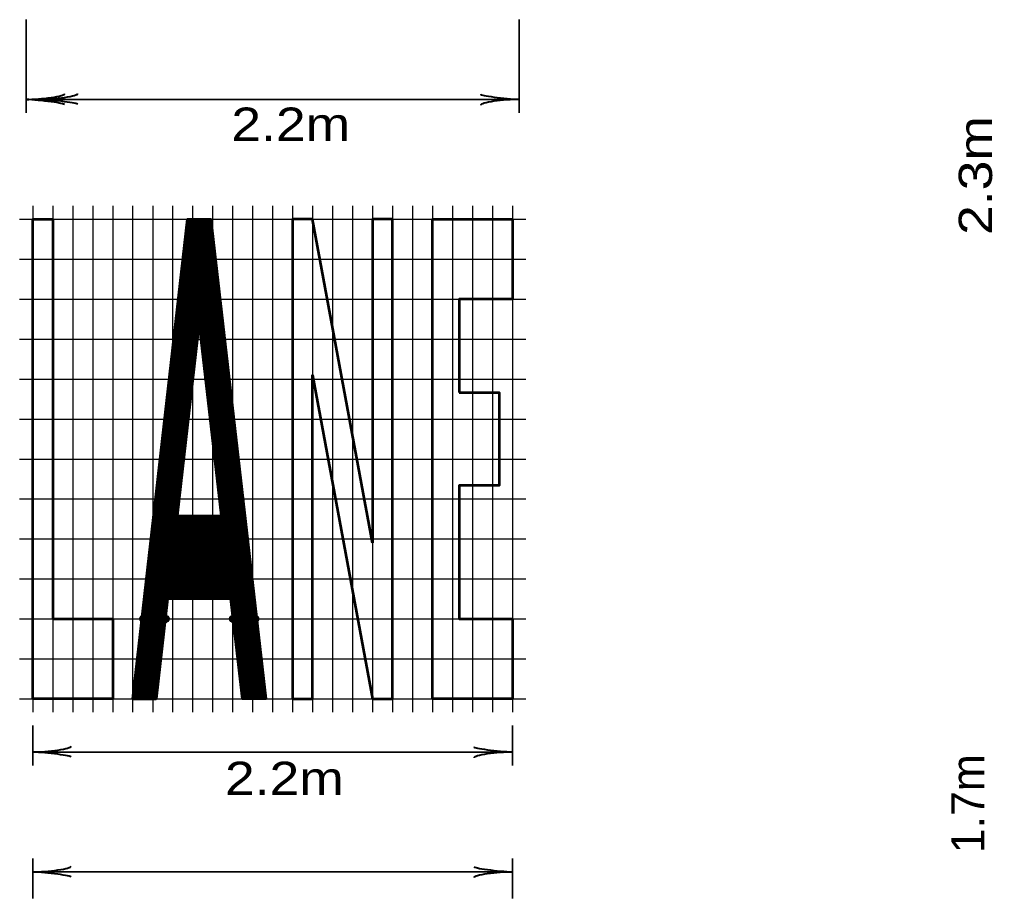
# Model space of a CAD drawing. Extents: x -96 to 617, y -65 to 388.
# Drawn here: x 37.8 to 110.8, y 261.3 to 327.3 of the extents above; entities that cross this region are included whole.
import ezdxf
from ezdxf.enums import TextEntityAlignment as Align

# ---------------------------------------------------------------- set-up
doc = ezdxf.new("R2010")
doc.units = 0
doc.header["$PDMODE"] = 32
doc.header["$PDSIZE"] = 0.5
doc.layers.add('1', color=7, linetype='Continuous', lineweight=53)

msp = doc.modelspace()

# ---------------------------------------------------------------- linework, layer by layer
at = {"layer": '1', "lineweight": 35}
for p, q in [((38.29, 327.267), (38.29, 320.267)), ((75.29, 327.267), (75.29, 320.267)), ((38.29, 321.267), (75.29, 321.267)), ((38.79, 274.267), (38.79, 271.267)), ((74.79, 274.267), (74.79, 271.267)), ((38.79, 272.267), (74.79, 272.267)), ((38.79, 264.267), (38.79, 261.267)), ((74.79, 264.267), (74.79, 261.267)), ((74.79, 263.267), (38.79, 263.267))]:
    msp.add_line(p, q, dxfattribs=at)
at = {"layer": '1', "lineweight": 25}
for p, q in [((38.79, 313.267), (38.79, 275.267)), ((40.29, 313.267), (40.29, 275.267)), ((41.79, 313.267), (41.79, 275.267)), ((43.29, 313.267), (43.29, 275.267)), ((44.79, 313.267), (44.79, 275.267)), ((46.29, 275.267), (46.29, 313.267)), ((47.79, 313.267), (47.79, 275.267)), ((49.29, 313.267), (49.29, 275.267)), ((50.79, 313.267), (50.79, 275.267)), ((52.29, 313.267), (52.29, 275.267)), ((53.79, 313.267), (53.79, 275.267)), ((55.29, 313.267), (55.29, 275.267)), ((56.79, 313.267), (56.79, 275.267)), ((58.29, 313.267), (58.29, 275.267)), ((59.79, 313.267), (59.79, 275.267)), ((61.29, 313.267), (61.29, 275.267)), ((62.79, 313.267), (62.79, 275.267)), ((64.29, 313.267), (64.29, 275.267)), ((65.79, 313.267), (65.79, 275.267)), ((67.29, 313.267), (67.29, 275.267)), ((68.79, 313.267), (68.79, 275.267)), ((70.29, 313.267), (70.29, 275.267)), ((71.79, 313.267), (71.79, 275.267)), ((73.29, 313.267), (73.29, 275.267)), ((74.79, 313.267), (74.79, 275.267)), ((37.79, 312.267), (75.79, 312.267)), ((37.79, 309.267), (75.79, 309.267)), ((37.79, 306.267), (75.79, 306.267)), ((37.79, 303.267), (75.79, 303.267)), ((37.79, 300.267), (75.79, 300.267)), ((37.79, 297.267), (75.79, 297.267)), ((37.79, 294.267), (75.79, 294.267)), ((37.79, 291.267), (75.79, 291.267)), ((37.79, 288.267), (75.79, 288.267)), ((37.79, 285.267), (75.79, 285.267)), ((37.79, 282.267), (75.79, 282.267)), ((37.79, 279.267), (75.79, 279.267)), ((37.79, 276.267), (75.79, 276.267))]:
    msp.add_line(p, q, dxfattribs=at)
at = {"layer": '1'}
for p, q in [((50.137, 309.84), (52.206, 311.91)), ((50.16, 310.04), (52.188, 312.068)), ((50.183, 310.24), (52.17, 312.227)), ((50.206, 310.44), (52.034, 312.267)), ((50.229, 310.639), (51.857, 312.267)), ((50.252, 310.839), (51.68, 312.267)), ((50.275, 311.038), (51.503, 312.267)), ((50.297, 311.238), (51.327, 312.267)), ((50.32, 311.438), (51.15, 312.267)), ((50.343, 311.637), (50.973, 312.267)), ((50.366, 311.837), (50.796, 312.267)), ((50.389, 312.037), (50.619, 312.267)), ((50.412, 312.236), (50.443, 312.267)), ((50.046, 309.042), (52.279, 311.275)), ((50.069, 309.242), (52.261, 311.434)), ((50.092, 309.441), (52.243, 311.592)), ((50.114, 309.641), (52.225, 311.751)), ((49.931, 308.044), (52.37, 310.482)), ((49.954, 308.243), (52.352, 310.641)), ((49.977, 308.443), (52.334, 310.799)), ((50, 308.643), (52.315, 310.958)), ((50.023, 308.842), (52.297, 311.116)), ((49.84, 307.245), (52.443, 309.848)), ((49.863, 307.445), (52.424, 310.006)), ((49.886, 307.644), (52.406, 310.165)), ((49.909, 307.844), (52.388, 310.323)), ((49.726, 306.247), (52.533, 309.055)), ((49.748, 306.446), (52.515, 309.213)), ((49.771, 306.646), (52.497, 309.372)), ((49.794, 306.846), (52.479, 309.531)), ((49.817, 307.045), (52.461, 309.689)), ((49.611, 305.248), (52.624, 308.262)), ((49.634, 305.448), (52.606, 308.42)), ((49.657, 305.648), (52.588, 308.579)), ((49.68, 305.847), (52.57, 308.738)), ((49.703, 306.047), (52.552, 308.896)), ((49.52, 304.45), (52.697, 307.627)), ((49.543, 304.649), (52.679, 307.786)), ((49.565, 304.849), (52.661, 307.945)), ((49.588, 305.049), (52.643, 308.103)), ((49.405, 303.452), (52.788, 306.834)), ((49.428, 303.651), (52.77, 306.993)), ((49.451, 303.851), (52.752, 307.151)), ((49.474, 304.051), (52.733, 307.31)), ((49.497, 304.25), (52.715, 307.469)), ((49.314, 302.653), (52.861, 306.2)), ((49.337, 302.853), (52.843, 306.358)), ((49.36, 303.052), (52.824, 306.517)), ((49.382, 303.252), (52.806, 306.676)), ((51.298, 304.461), (52.879, 306.041)), ((51.317, 304.302), (52.897, 305.883)), ((51.335, 304.144), (52.915, 305.724)), ((51.353, 303.985), (52.933, 305.565)), ((51.371, 303.826), (52.951, 305.407)), ((51.389, 303.668), (52.97, 305.248)), ((51.407, 303.509), (52.988, 305.09)), ((51.426, 303.351), (53.006, 304.931)), ((51.444, 303.192), (53.024, 304.772)), ((51.462, 303.033), (53.042, 304.614)), ((49.245, 302.054), (51.235, 304.043)), ((49.268, 302.254), (51.257, 304.243)), ((49.291, 302.453), (51.28, 304.443)), ((51.48, 302.875), (53.06, 304.455)), ((51.498, 302.716), (53.079, 304.297)), ((51.517, 302.558), (53.097, 304.138)), ((51.535, 302.399), (53.115, 303.979)), ((49.154, 301.255), (51.143, 303.245)), ((49.176, 301.455), (51.166, 303.445)), ((49.199, 301.655), (51.189, 303.644)), ((49.222, 301.854), (51.212, 303.844)), ((51.553, 302.24), (53.133, 303.821)), ((51.571, 302.082), (53.151, 303.662)), ((51.589, 301.923), (53.17, 303.504)), ((51.607, 301.765), (53.188, 303.345)), ((51.626, 301.606), (53.206, 303.186)), ((49.062, 300.457), (51.051, 302.446)), ((49.085, 300.656), (51.074, 302.646)), ((49.108, 300.856), (51.097, 302.846)), ((49.131, 301.056), (51.12, 303.045)), ((51.644, 301.447), (53.224, 303.028)), ((51.662, 301.289), (53.242, 302.869)), ((51.68, 301.13), (53.26, 302.711)), ((51.698, 300.972), (53.279, 302.552)), ((48.993, 299.858), (50.983, 301.847)), ((49.016, 300.058), (51.006, 302.047)), ((49.039, 300.257), (51.029, 302.246)), ((51.716, 300.813), (53.297, 302.393)), ((51.735, 300.654), (53.315, 302.235)), ((51.753, 300.496), (53.333, 302.076)), ((51.771, 300.337), (53.351, 301.918)), ((51.789, 300.179), (53.369, 301.759)), ((48.902, 299.059), (50.891, 301.049)), ((48.925, 299.259), (50.914, 301.248)), ((48.948, 299.459), (50.937, 301.448)), ((48.971, 299.658), (50.96, 301.648)), ((51.807, 300.02), (53.388, 301.6)), ((51.825, 299.861), (53.406, 301.442)), ((51.844, 299.703), (53.424, 301.283)), ((51.862, 299.544), (53.442, 301.125)), ((51.88, 299.385), (53.46, 300.966)), ((48.81, 298.261), (50.8, 300.25)), ((48.833, 298.46), (50.823, 300.45)), ((48.856, 298.66), (50.846, 300.649)), ((48.879, 298.86), (50.868, 300.849)), ((51.898, 299.227), (53.478, 300.807)), ((51.916, 299.068), (53.497, 300.649)), ((51.934, 298.91), (53.515, 300.49)), ((51.953, 298.751), (53.533, 300.332)), ((48.742, 297.662), (50.731, 299.651)), ((48.765, 297.861), (50.754, 299.851)), ((48.788, 298.061), (50.777, 300.05)), ((51.971, 298.592), (53.551, 300.173)), ((51.989, 298.434), (53.569, 300.014)), ((52.007, 298.275), (53.588, 299.856)), ((52.025, 298.117), (53.606, 299.697)), ((52.044, 297.958), (53.624, 299.538)), ((48.65, 296.863), (50.64, 298.852)), ((48.673, 297.063), (50.663, 299.052)), ((48.696, 297.262), (50.685, 299.252)), ((48.719, 297.462), (50.708, 299.451)), ((52.062, 297.799), (53.642, 299.38)), ((52.08, 297.641), (53.66, 299.221)), ((52.098, 297.482), (53.678, 299.063)), ((52.116, 297.324), (53.697, 298.904)), ((48.559, 296.064), (50.548, 298.054)), ((48.582, 296.264), (50.571, 298.253)), ((48.605, 296.464), (50.594, 298.453)), ((48.627, 296.663), (50.617, 298.653)), ((52.134, 297.165), (53.715, 298.745)), ((52.153, 297.007), (53.733, 298.587)), ((52.171, 296.848), (53.751, 298.428)), ((52.189, 296.689), (53.769, 298.27)), ((52.207, 296.531), (53.788, 298.111)), ((48.49, 295.465), (50.48, 297.455)), ((48.513, 295.665), (50.502, 297.654)), ((48.536, 295.865), (50.525, 297.854)), ((52.225, 296.372), (53.806, 297.952)), ((52.243, 296.214), (53.824, 297.794)), ((52.262, 296.055), (53.842, 297.635)), ((52.28, 295.896), (53.86, 297.477)), ((52.298, 295.738), (53.878, 297.318)), ((48.399, 294.667), (50.388, 296.656)), ((48.422, 294.866), (50.411, 296.856)), ((48.444, 295.066), (50.434, 297.055)), ((48.467, 295.266), (50.457, 297.255)), ((52.316, 295.579), (53.896, 297.159)), ((52.334, 295.42), (53.915, 297.001)), ((52.352, 295.262), (53.933, 296.842)), ((52.371, 295.103), (53.951, 296.684)), ((48.307, 293.868), (50.297, 295.858)), ((48.33, 294.068), (50.319, 296.057)), ((48.353, 294.267), (50.342, 296.257)), ((48.376, 294.467), (50.365, 296.457)), ((52.389, 294.945), (53.969, 296.525)), ((52.407, 294.786), (53.987, 296.366)), ((52.425, 294.627), (54.006, 296.208)), ((52.443, 294.469), (54.024, 296.049)), ((52.462, 294.31), (54.042, 295.891)), ((48.239, 293.269), (50.228, 295.259)), ((48.261, 293.469), (50.251, 295.458)), ((48.284, 293.669), (50.274, 295.658)), ((52.48, 294.152), (54.06, 295.732)), ((52.498, 293.993), (54.078, 295.573)), ((52.516, 293.834), (54.096, 295.415)), ((52.534, 293.676), (54.115, 295.256)), ((48.147, 292.471), (50.136, 294.46)), ((48.17, 292.67), (50.159, 294.66)), ((48.193, 292.87), (50.182, 294.859)), ((48.216, 293.07), (50.205, 295.059)), ((52.552, 293.517), (54.133, 295.098)), ((52.571, 293.359), (54.151, 294.939)), ((52.589, 293.2), (54.169, 294.78)), ((52.607, 293.041), (54.187, 294.622)), ((52.625, 292.883), (54.205, 294.463)), ((48.056, 291.672), (50.045, 293.661)), ((48.078, 291.872), (50.068, 293.861)), ((48.101, 292.071), (50.091, 294.061)), ((48.124, 292.271), (50.113, 294.26)), ((52.643, 292.724), (54.224, 294.305)), ((52.661, 292.566), (54.242, 294.146)), ((52.68, 292.407), (54.26, 293.987)), ((52.698, 292.248), (54.278, 293.829)), ((52.716, 292.09), (54.296, 293.67)), ((47.987, 291.073), (49.976, 293.062)), ((48.01, 291.273), (49.999, 293.262)), ((48.033, 291.472), (50.022, 293.462)), ((52.734, 291.931), (54.314, 293.512)), ((52.752, 291.773), (54.333, 293.353)), ((52.77, 291.614), (54.351, 293.194)), ((52.789, 291.455), (54.369, 293.036)), ((47.895, 290.274), (49.885, 292.264)), ((47.918, 290.474), (49.908, 292.463)), ((47.941, 290.674), (49.93, 292.663)), ((47.964, 290.873), (49.953, 292.863)), ((52.807, 291.297), (54.387, 292.877)), ((52.825, 291.138), (54.405, 292.719)), ((52.843, 290.98), (54.423, 292.56)), ((52.861, 290.821), (54.442, 292.401)), ((52.88, 290.662), (54.46, 292.243)), ((47.804, 289.476), (49.793, 291.465)), ((47.827, 289.675), (49.816, 291.665)), ((47.85, 289.875), (49.839, 291.864)), ((47.873, 290.075), (49.862, 292.064)), ((52.898, 290.504), (54.478, 292.084)), ((52.916, 290.345), (54.496, 291.925)), ((52.934, 290.186), (54.514, 291.767)), ((52.952, 290.028), (54.533, 291.608)), ((47.095, 283.287), (54.623, 290.815)), ((47.118, 283.486), (54.605, 290.974)), ((47.14, 283.686), (54.587, 291.132)), ((47.163, 283.885), (54.569, 291.291)), ((47.186, 284.085), (54.551, 291.45)), ((47.735, 288.877), (49.725, 290.866)), ((47.758, 289.077), (49.747, 291.066)), ((47.781, 289.276), (49.77, 291.265)), ((46.98, 282.288), (54.714, 290.022)), ((47.003, 282.488), (54.696, 290.181)), ((47.026, 282.688), (54.678, 290.339)), ((47.049, 282.887), (54.66, 290.498)), ((47.072, 283.087), (54.642, 290.657)), ((47.209, 284.285), (52.919, 289.995)), ((47.232, 284.484), (52.742, 289.995)), ((47.255, 284.684), (52.566, 289.995)), ((47.278, 284.884), (52.389, 289.995)), ((47.301, 285.084), (52.212, 289.995)), ((47.323, 285.283), (52.035, 289.995)), ((47.346, 285.483), (51.858, 289.995)), ((47.369, 285.682), (51.682, 289.995)), ((47.392, 285.882), (51.505, 289.995)), ((47.415, 286.082), (51.328, 289.995)), ((47.438, 286.281), (51.151, 289.995)), ((47.461, 286.481), (50.974, 289.995)), ((47.484, 286.681), (50.798, 289.995)), ((47.506, 286.88), (50.621, 289.995)), ((47.529, 287.08), (50.444, 289.995)), ((47.552, 287.28), (50.267, 289.995)), ((47.575, 287.479), (50.091, 289.995)), ((47.598, 287.679), (49.914, 289.995)), ((47.621, 287.879), (49.737, 289.995)), ((47.644, 288.078), (49.633, 290.068)), ((47.667, 288.278), (49.656, 290.267)), ((47.689, 288.478), (49.679, 290.467)), ((47.712, 288.677), (49.702, 290.667)), ((47.136, 282.267), (54.733, 289.864)), ((47.313, 282.267), (54.751, 289.705)), ((48.997, 283.775), (54.769, 289.546)), ((49.174, 283.775), (54.787, 289.388)), ((49.351, 283.775), (54.805, 289.229)), ((49.527, 283.775), (54.823, 289.071)), ((49.704, 283.775), (54.841, 288.912)), ((49.881, 283.775), (54.86, 288.753)), ((50.058, 283.775), (54.878, 288.595)), ((50.235, 283.775), (54.896, 288.436)), ((50.411, 283.775), (54.914, 288.278)), ((50.588, 283.775), (54.932, 288.119)), ((50.765, 283.775), (54.951, 287.96)), ((50.942, 283.775), (54.969, 287.802)), ((51.118, 283.775), (54.987, 287.643)), ((51.295, 283.775), (55.005, 287.485)), ((51.472, 283.775), (55.023, 287.326)), ((51.649, 283.775), (55.041, 287.167)), ((51.825, 283.775), (55.06, 287.009)), ((52.002, 283.775), (55.078, 286.85)), ((52.179, 283.775), (55.096, 286.692)), ((52.356, 283.775), (55.114, 286.533)), ((52.533, 283.775), (55.132, 286.374)), ((52.709, 283.775), (55.151, 286.216)), ((52.886, 283.775), (55.169, 286.057)), ((53.063, 283.775), (55.187, 285.899)), ((53.24, 283.775), (55.205, 285.74)), ((53.416, 283.775), (55.223, 285.581)), ((53.593, 283.775), (55.241, 285.423)), ((53.679, 283.684), (55.259, 285.264)), ((53.697, 283.525), (55.278, 285.106)), ((53.715, 283.367), (55.296, 284.947)), ((53.734, 283.208), (55.314, 284.788)), ((53.752, 283.049), (55.332, 284.63)), ((53.77, 282.891), (55.35, 284.471)), ((53.788, 282.732), (55.369, 284.313)), ((53.806, 282.573), (55.387, 284.154)), ((47.489, 282.267), (48.901, 283.679)), ((47.666, 282.267), (48.878, 283.479)), ((53.825, 282.415), (55.405, 283.995)), ((53.853, 282.267), (55.423, 283.837)), ((54.03, 282.267), (55.441, 283.678)), ((54.207, 282.267), (55.459, 283.519)), ((47.843, 282.267), (48.855, 283.279)), ((48.02, 282.267), (48.832, 283.08)), ((48.197, 282.267), (48.81, 282.88)), ((54.384, 282.267), (55.478, 283.361)), ((54.561, 282.267), (55.496, 283.202)), ((54.737, 282.267), (55.514, 283.044)), ((54.914, 282.267), (55.532, 282.885)), ((55.091, 282.267), (55.55, 282.726)), ((46.729, 280.092), (48.718, 282.082)), ((46.752, 280.292), (48.727, 282.267)), ((46.774, 280.491), (48.55, 282.267)), ((46.797, 280.691), (48.373, 282.267)), ((46.82, 280.891), (48.197, 282.267)), ((46.843, 281.09), (48.02, 282.267)), ((46.866, 281.29), (47.843, 282.267)), ((46.889, 281.49), (47.666, 282.267)), ((46.912, 281.689), (47.489, 282.267)), ((46.935, 281.889), (47.313, 282.267)), ((46.957, 282.089), (47.136, 282.267)), ((48.373, 282.267), (48.787, 282.68)), ((48.55, 282.267), (48.764, 282.481)), ((48.727, 282.267), (48.741, 282.281)), ((53.843, 282.256), (53.853, 282.267)), ((53.861, 282.098), (54.03, 282.267)), ((53.879, 281.939), (54.207, 282.267)), ((53.897, 281.781), (54.384, 282.267)), ((53.915, 281.622), (54.561, 282.267)), ((53.933, 281.463), (54.737, 282.267)), ((53.952, 281.305), (54.914, 282.267)), ((53.97, 281.146), (55.091, 282.267)), ((53.988, 280.988), (55.268, 282.267)), ((54.006, 280.829), (55.444, 282.267)), ((54.024, 280.67), (55.605, 282.251)), ((54.043, 280.512), (55.623, 282.092)), ((55.268, 282.267), (55.568, 282.568)), ((55.444, 282.267), (55.587, 282.409)), ((46.637, 279.293), (48.627, 281.283)), ((46.66, 279.493), (48.649, 281.483)), ((46.683, 279.693), (48.672, 281.682)), ((46.706, 279.892), (48.695, 281.882)), ((54.061, 280.353), (55.641, 281.933)), ((54.079, 280.195), (55.659, 281.775)), ((54.097, 280.036), (55.677, 281.616)), ((54.115, 279.877), (55.696, 281.458)), ((54.133, 279.719), (55.714, 281.299)), ((46.569, 278.695), (48.558, 280.684)), ((46.591, 278.894), (48.581, 280.884)), ((46.614, 279.094), (48.604, 281.083)), ((54.152, 279.56), (55.732, 281.14)), ((54.17, 279.401), (55.75, 280.982)), ((54.188, 279.243), (55.768, 280.823)), ((54.206, 279.084), (55.786, 280.665)), ((54.224, 278.926), (55.805, 280.506)), ((46.477, 277.896), (48.466, 279.885)), ((46.5, 278.096), (48.489, 280.085)), ((46.523, 278.295), (48.512, 280.285)), ((46.546, 278.495), (48.535, 280.484)), ((54.242, 278.767), (55.823, 280.347)), ((54.261, 278.608), (55.841, 280.189)), ((54.279, 278.45), (55.859, 280.03)), ((54.297, 278.291), (55.877, 279.872)), ((46.386, 277.097), (48.375, 279.087)), ((46.408, 277.297), (48.398, 279.286)), ((46.431, 277.497), (48.421, 279.486)), ((46.454, 277.696), (48.444, 279.686)), ((54.315, 278.133), (55.896, 279.713)), ((54.333, 277.974), (55.914, 279.554)), ((54.352, 277.815), (55.932, 279.396)), ((54.37, 277.657), (55.95, 279.237)), ((54.388, 277.498), (55.968, 279.079)), ((46.317, 276.498), (48.306, 278.488)), ((46.34, 276.698), (48.329, 278.687)), ((46.363, 276.898), (48.352, 278.887)), ((54.406, 277.34), (55.986, 278.92)), ((54.424, 277.181), (56.005, 278.761)), ((54.442, 277.022), (56.023, 278.603)), ((54.461, 276.864), (56.041, 278.444)), ((46.294, 276.299), (48.283, 278.288)), ((46.439, 276.267), (48.261, 278.088)), ((46.616, 276.267), (48.238, 277.889)), ((46.793, 276.267), (48.215, 277.689)), ((54.479, 276.705), (56.059, 278.286)), ((54.497, 276.547), (56.077, 278.127)), ((54.515, 276.388), (56.096, 277.968)), ((54.571, 276.267), (56.114, 277.81)), ((54.748, 276.267), (56.132, 277.651)), ((46.97, 276.267), (48.192, 277.489)), ((47.146, 276.267), (48.169, 277.29)), ((47.323, 276.267), (48.146, 277.09)), ((47.5, 276.267), (48.123, 276.89)), ((54.925, 276.267), (56.15, 277.493)), ((55.101, 276.267), (56.168, 277.334)), ((55.278, 276.267), (56.186, 277.175)), ((55.455, 276.267), (56.204, 277.017)), ((55.632, 276.267), (56.223, 276.858)), ((46.29, 276.267), (48.052, 276.267)), ((47.677, 276.267), (48.1, 276.691)), ((47.853, 276.267), (48.078, 276.491)), ((48.03, 276.267), (48.055, 276.291)), ((55.808, 276.267), (56.241, 276.7)), ((55.985, 276.267), (56.259, 276.541)), ((56.162, 276.267), (56.277, 276.382))]:
    msp.add_line(p, q, dxfattribs=at)
for points in [[(40.29, 312.267), (40.29, 282.267), (44.79, 282.267), (44.79, 276.267), (38.79, 276.267), (38.79, 312.267)], [(46.29, 276.267), (50.415, 312.267), (52.165, 312.267), (56.29, 276.267), (54.529, 276.267), (53.669, 283.775), (48.912, 283.775), (48.052, 276.267)], [(64.29, 287.967), (59.79, 312.267), (58.29, 312.267), (58.29, 276.267), (59.79, 276.267), (59.79, 300.567), (64.29, 276.267), (65.79, 276.267), (65.79, 312.267), (64.29, 312.267)], [(70.79, 299.267), (73.79, 299.267), (73.79, 292.267), (70.79, 292.267), (70.79, 282.267), (74.79, 282.267), (74.79, 276.267), (68.79, 276.267), (68.79, 312.267), (74.79, 312.267), (74.79, 306.267), (70.79, 306.267)], [(51.29, 304.531), (49.625, 289.995), (52.956, 289.995)]]:
    msp.add_lwpolyline(points, close=True, dxfattribs=at)
at = {"layer": '1', "lineweight": 40}
for centre, major_axis, ratio, start_param, end_param in [((39.391, 321.535), (-1.786, -0.156), 0.122415, 0.896353, 3.141593), ((40.382, 321.543), (-1.786, -0.156), 0.122415, 0.896353, 3.141593), ((74.17, 321.479), (1.756, -0.176), 0.07063, 3.140715, 5.41811), ((39.42, 321.047), (-1.756, 0.176), 0.07063, 3.140715, 5.41811), ((40.411, 321.056), (-1.756, 0.176), 0.07063, 3.140715, 5.41811), ((74.199, 320.991), (1.786, 0.156), 0.122415, 0.896353, 3.141593), ((39.882, 272.543), (-1.786, -0.156), 0.122415, 0.896353, 3.141593), ((39.882, 272.543), (-1.786, -0.156), 0.122415, 0.896353, 3.141593), ((73.67, 272.479), (1.756, -0.176), 0.07063, 3.140715, 5.41811), ((73.67, 272.479), (1.756, -0.176), 0.07063, 3.140715, 5.41811), ((39.911, 272.056), (-1.756, 0.176), 0.07063, 3.140715, 5.41811), ((39.911, 272.056), (-1.756, 0.176), 0.07063, 3.140715, 5.41811), ((73.699, 271.991), (1.786, 0.156), 0.122415, 0.896353, 3.141593), ((73.699, 271.991), (1.786, 0.156), 0.122415, 0.896353, 3.141593), ((39.882, 263.543), (-1.786, -0.156), 0.122415, 0.896353, 3.141593), ((39.911, 263.056), (-1.756, 0.176), 0.07063, 3.140715, 5.41811), ((73.699, 262.991), (1.786, 0.156), 0.122415, 0.896353, 3.141593), ((73.699, 262.991), (1.786, 0.156), 0.122415, 0.896353, 3.141593), ((73.67, 263.479), (1.756, -0.176), 0.07063, 3.140715, 5.41811), ((73.67, 263.479), (1.756, -0.176), 0.07063, 3.140715, 5.41811)]:
    msp.add_ellipse(centre, major_axis=major_axis, ratio=ratio, start_param=start_param, end_param=end_param, dxfattribs=at)
at = {"layer": '1'}
for p in [(47.136, 282.267), (47.313, 282.267), (47.489, 282.267), (47.666, 282.267), (47.843, 282.267), (48.02, 282.267), (48.197, 282.267), (48.373, 282.267), (48.55, 282.267), (48.727, 282.267), (53.853, 282.267), (54.03, 282.267), (54.207, 282.267), (54.384, 282.267), (54.561, 282.267), (54.737, 282.267), (54.914, 282.267), (55.091, 282.267), (55.268, 282.267), (55.444, 282.267)]:
    msp.add_point(p, dxfattribs=at)

# ---------------------------------------------------------------- texts
at = {"layer": '1', "width": 1.2}
for p in [(53.695, 318.152), (53.216, 269.041)]:
    msp.add_text('2.2m', height=2.5, dxfattribs=at).set_placement(p)
msp.add_text('2.3m', height=2.5, rotation=90, dxfattribs=at).set_placement((110.8, 315.553), align=Align.CENTER)
at = {"layer": '1'}
msp.add_text('1.7m', height=2.5, rotation=90, dxfattribs=at).set_placement((110.231, 268.391), align=Align.CENTER)

doc.saveas('drawing.dxf')
